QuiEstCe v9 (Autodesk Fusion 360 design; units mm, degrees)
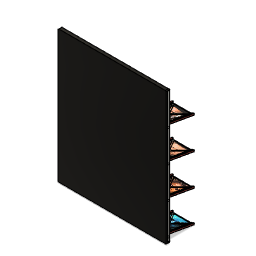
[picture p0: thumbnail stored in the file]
sketch "Esquisse1" plane through (0, 0, 0) normal (0, 1, 0) x axis (1, 0, 0)
  line L1 (15.9126, 24.8052) -> (-7.0874, 24.8052)
  line L2 (15.9126, -7.1948) -> (15.9126, 24.8052)
  line L3 (-7.0874, -7.1948) -> (15.9126, -7.1948)
  line L4 (-7.0874, 24.8052) -> (-7.0874, -7.1948)
  line L5 (16.9126, 25.8052) -> (-8.0874, 25.8052)
  line L6 (16.9126, -9.1948) -> (16.9126, 25.8052)
  line L7 (-8.0874, -9.1948) -> (16.9126, -9.1948)
  line L8 (-8.0874, 25.8052) -> (-8.0874, -9.1948)
  line L9 (-7.0874, 25.8052) -> (-7.0874, 24.8052)
  line L10 (15.9126, 25.8052) -> (15.9126, 24.8052)
  line L11 (14.9126, 24.8052) -> (-6.0874, 24.8052)
  line L12 (14.9126, -7.1948) -> (14.9126, 24.8052)
  line L13 (-6.0874, -7.1948) -> (14.9126, -7.1948)
  line L14 (-6.0874, 24.8052) -> (-6.0874, -7.1948)
  line L15 (15, -7.1948) -> (-7.0874, -7.1948)
  line L16 (15, -8.1948) -> (15, -7.1948)
  line L17 (-7.0874, -8.1948) -> (15, -8.1948)
  line L18 (-7.0874, -7.1948) -> (-7.0874, -8.1948)
  line L19 (13.9126, -7.1948) -> (-6.0874, 23.8052)
  line L20 (14.9126, -6.1948) -> (-5.0874, 24.8052)
  line L21 (-6.0874, -6.1948) -> (13.9126, 24.8052)
  line L22 (14.9126, 23.8052) -> (-5.0874, -7.1948)
  line L23 (14.6866, 25.7994) -> (-5.8002, 25.7994)
  line L24 (15.6866, -7.1031) -> (15.6866, 24.7994)
  line L25 (-5.8002, -8.1031) -> (14.6866, -8.1031)
  line L26 (-6.8002, 24.7994) -> (-6.8002, -7.1031)
  arc A1 centre (-5.8002, 24.7994) radius 1 clockwise from (-6.8002, 24.7994) to (-5.8002, 25.7994)
  arc A2 centre (14.6866, 24.7994) radius 1 clockwise from (14.6866, 25.7994) to (15.6866, 24.7994)
  arc A3 centre (-5.8002, -7.1031) radius 1 clockwise from (-5.8002, -8.1031) to (-6.8002, -7.1031)
  arc A4 centre (14.6866, -7.1031) radius 1 clockwise from (15.6866, -7.1031) to (14.6866, -8.1031)
  point P10 (-7.0874, 25.8052)
  point P11 (15.9126, 25.8052)
  point P14 (14.9126, -7.1948)
  point P12 (-6.0874, 24.8052)
  point P19 (-6.0874, 23.8052)
  point P20 (13.9126, -7.1948)
  point P21 (-5.0874, 24.8052)
  point P22 (14.9126, -6.1948)
  point P23 (13.9126, 24.8052)
  point P24 (-6.0874, -6.1948)
  point P25 (-5.0874, -7.1948)
  point P26 (14.9126, 23.8052)
  horizontal L1
  vertical L2
  horizontal L3
  vertical L4
  horizontal L5
  vertical L6
  horizontal L7
  vertical L8
  coincident L5 P10
  perpendicular L5 L9
  coincident L5 P11
  perpendicular L5 L10
  horizontal L11
  vertical L12
  horizontal L13
  vertical L14
  coincident L3 P14
  coincident L1 P12
  horizontal L15
  vertical L16
  horizontal L17
  vertical L18
  coincident L14 P19
  coincident L15 P20
  coincident L1 P21
  coincident L12 P22
  parallel L19 L20
  coincident L1 P23
  coincident L14 P24
  coincident L15 P25
  coincident L12 P26
  parallel L21 L22
  horizontal L23
  vertical L24
  horizontal L25
  vertical L26
  tangent L23 A1
  tangent L26 A1
  tangent L23 A2
  tangent L24 A2
  equal A1 A2
  tangent L26 A3
  tangent L25 A3
  equal A1 A3
  tangent L25 A4
  tangent L24 A4
  equal A1 A4
  dimension "d5" distance L4 L14 = 1
  dimension "d6" distance L2 L12 = 1
  dimension "d7" distance L4 L8 = 1
  dimension "d8" distance L2 L6 = 1
  dimension "d11" distance L3 L17 = 1
  dimension "d18" distance L6 L8 = 25
  dimension "d19" distance L5 L7 = 35
  dimension "d20" distance L7 L17 = 1
  dimension "d21" distance L5 L11 = 1
  dimension "d24" distance L11 P26 = 1
  dimension "d25" distance L12 P23 = 1
  dimension "d26" distance L14 P21 = 1
  dimension "d27" distance L1 P19 = 1
  dimension "d28" distance L3 P24 = 1
  dimension "d29" distance L15 P22 = 1
  dimension "d75" radius A1 = 1
extrude "Extrusion1" new body sketch "Esquisse1" profile of L1 L2 L3 L4 L5 L6 L7 L8 L9 L10 L11 L12 L13 L14 L15 L16 L17 L18 L19 L20 L21 L22 against normal blind 1
extrude "Extrusion2" add sketch "Esquisse1" profile of L1 L2 L3 L4 L5 L6 L7 L8 L9 L10 L12 L13 L14 along normal blind 1.5
extrude "Extrusion3" cut sketch "Esquisse1" profile of L1 L2 L3 L4 L12 L13 L14 L15 L16 L17 L18 along normal blind 1
chamfer "Chanfrein" distance 0.4 Rotate Angle 80
sketch "Esquisse2" plane through (16.9126, 0, 0) normal (1, 0, 0) x axis (0, 0, -1)
  line L1 (-9.1948, 1.2685) -> (-9.1948, 1.5)
  line L2 (25.8052, -1) -> (-8.7948, -1)
  line L3 (25.8052, 1.5) -> (25.8052, -1)
  line L4 (-9.1948, 1.5) -> (25.8052, 1.5)
  line L5 (-6.6948, 1.5) -> (-7.7948, 1.5)
  line L6 (-6.6948, -1) -> (-6.6948, 1.5)
  line L7 (-9.1948, -1) -> (-6.6948, -1)
  line L8 (-9.1948, 0.1) -> (-9.1948, -1)
  line L9 (-6.6948, -1) -> (-9.1948, 1.5)
  line L10 (-8.7948, -1) -> (-6.6948, 1.5)
  line L11 (-8.7948, -1) -> (-9.1948, 1.2685)
  circle C1 centre (-7.7448, 0.25) radius 0.75
  arc A1 centre (-7.7948, 0.1) radius 1.4 clockwise from (-9.1948, 0.1) to (-7.7948, 1.5)
  point P7 (-6.6948, -1)
  point P2 (-9.1948, 1.5)
  point P9 (-9.1948, 1.5)
  point P3 (-8.7948, -1)
  point P10 (-8.7948, -1)
  point P11 (-7.7448, 0.25)
  horizontal L5
  vertical L6
  horizontal L7
  vertical L8
  coincident L2 P7
  coincident P2 P9
  coincident P3 P10
  midpoint L10 P11
  tangent L8 A1
  tangent L5 A1
  dimension "d12" distance L6 L8 = 2.5
  dimension "d13" diameter C1 = 1.5
  dimension "d43" radius A1 = 1.4
extrude "Extrusion4" new body sketch "Esquisse2" profile of C1 along normal blind 1.5
extrude "Extrusion10" cut sketch "Esquisse2" profile of L1 L4 L11 A1 against normal blind 25.2
fillet "Congé1" radius 0.5
copy_paste_bodies "Copier/Coller des corps1"
move "Déplacer1"
combine "Combiner1"
move "Déplacer2"
combine "Combiner2"
fillet "Congé5" radius 1
fillet "Congé6" radius 1.25
fillet "Congé7" radius 0.4
move "Déplacer3"
copy_paste_bodies "Copier/Coller des corps2"
move "Déplacer4"
copy_paste_bodies "Copier/Coller des corps3"
move "Déplacer5"
copy_paste_bodies "Copier/Coller des corps4"
move "Déplacer6"
move "Déplacer7"
copy_paste_bodies "Copier/Coller des corps5"
move "Déplacer8"
copy_paste_bodies "Copier/Coller des corps6"
move "Déplacer9"
copy_paste_bodies "Copier/Coller des corps7"
move "Déplacer10"
extrude "Extrusion5" new body blind 1.5
sketch "Esquisse4" plane through (0, 37.8052, 0) normal (0, 1, 0) x axis (-1, 0, 0)
  line L1 (97.0874, 0) -> (-25.9126, 0)
  line L2 (97.0874, 1.5) -> (97.0874, 0)
  line L3 (-25.9126, 1.5) -> (97.0874, 1.5)
  line L4 (-25.9126, 0) -> (-25.9126, 1.5)
  line L5 (93.5874, 0) -> (97.0874, 0)
  line L6 (93.5874, -2.5) -> (93.5874, 0)
  line L7 (96.5874, -3) -> (94.0874, -3)
  line L8 (97.0874, 0) -> (97.0874, -2.5)
  line L9 (64.0874, -3) -> (67.0874, -3)
  line L10 (63.5874, 0) -> (63.5874, -2.5)
  line L11 (67.5874, 0) -> (63.5874, 0)
  line L12 (67.5874, -2.5) -> (67.5874, 0)
  line L13 (33.5874, 0) -> (37.5874, 0)
  line L14 (33.5874, -2.5) -> (33.5874, 0)
  line L15 (37.0874, -3) -> (34.0874, -3)
  line L16 (37.5874, 0) -> (37.5874, -2.5)
  line L17 (3.5874, 0) -> (7.5874, 0)
  line L18 (3.5874, -2.5) -> (3.5874, 0)
  line L19 (7.0874, -3) -> (4.0874, -3)
  line L20 (7.5874, 0) -> (7.5874, -2.5)
  line L21 (-22.4126, 0) -> (-25.9126, 0)
  line L22 (-22.4126, -2.5) -> (-22.4126, 0)
  line L23 (-25.4126, -3) -> (-22.9126, -3)
  line L24 (-25.9126, 0) -> (-25.9126, -2.5)
  line L25 (-24.4, -3) -> (96.6703, -3)
  line L26 (-25.4126, 0) -> (-25.4126, -3)
  line L27 (3.0874, -23.8052) -> (3.0874, 9.0481)
  line L28 (-21.9126, 9.0377) -> (-21.9126, -23.8052)
  line L29 (93.0874, -23.8052) -> (93.0874, 9.0481)
  line L30 (63.0874, -23.8052) -> (63.0874, 9.0481)
  line L31 (68.0874, 9.0377) -> (68.0874, -23.8052)
  line L32 (38.0874, 9.0377) -> (38.0874, -23.8052)
  line L33 (97.0874, 0) -> (-25.9126, 0)
  arc A1 centre (96.5874, -2.5) radius 0.5 clockwise from (97.0874, -2.5) to (96.5874, -3)
  arc A2 centre (94.0874, -2.5) radius 0.5 clockwise from (94.0874, -3) to (93.5874, -2.5)
  arc A3 centre (67.0874, -2.5) radius 0.5 clockwise from (67.5874, -2.5) to (67.0874, -3)
  arc A4 centre (64.0874, -2.5) radius 0.5 clockwise from (64.0874, -3) to (63.5874, -2.5)
  arc A5 centre (37.0874, -2.5) radius 0.5 clockwise from (37.5874, -2.5) to (37.0874, -3)
  arc A6 centre (34.0874, -2.5) radius 0.5 clockwise from (34.0874, -3) to (33.5874, -2.5)
  arc A7 centre (7.0874, -2.5) radius 0.5 clockwise from (7.5874, -2.5) to (7.0874, -3)
  arc A8 centre (4.0874, -2.5) radius 0.5 clockwise from (4.0874, -3) to (3.5874, -2.5)
  arc A9 centre (-22.9126, -2.5) radius 0.5 clockwise from (-22.4126, -2.5) to (-22.9126, -3)
  arc A10 centre (-25.4126, -2.5) radius 0.5 clockwise from (-25.4126, -3) to (-25.9126, -2.5)
  point P3 (97.0874, 0)
  point P6 (97.0874, 0)
  point P8 (63.5874, 0)
  point P10 (37.5874, 0)
  point P12 (7.5874, 0)
  point P2 (-25.9126, 0)
  point P14 (-25.9126, 0)
  point P46 (96.6703, -3)
  point P47 (-24.4, -3)
  point P48 (-25.4126, 0)
  horizontal L5
  vertical L6
  horizontal L7
  vertical L8
  coincident P3 P6
  horizontal L9
  vertical L10
  horizontal L11
  vertical L12
  coincident L1 P8
  horizontal L13
  vertical L14
  horizontal L15
  vertical L16
  coincident L1 P10
  horizontal L17
  vertical L18
  horizontal L19
  vertical L20
  coincident L1 P12
  horizontal L21
  vertical L22
  horizontal L23
  vertical L24
  coincident P2 P14
  tangent L8 A1
  tangent L7 A1
  tangent L7 A2
  tangent L6 A2
  equal A1 A2
  tangent L12 A3
  tangent L9 A3
  equal A1 A3
  tangent L9 A4
  tangent L10 A4
  equal A1 A4
  tangent L16 A5
  tangent L15 A5
  equal A1 A5
  tangent L15 A6
  tangent L14 A6
  equal A1 A6
  tangent L20 A7
  tangent L19 A7
  equal A1 A7
  tangent L19 A8
  tangent L18 A8
  equal A1 A8
  tangent L22 A9
  tangent L23 A9
  equal A1 A9
  tangent L23 A10
  tangent L24 A10
  equal A1 A10
  coincident L7 P46
  coincident L23 P47
  perpendicular L6 L25
  coincident L21 P48
  collinear L9 L25
  collinear L19 L25
  collinear L15 L25
  parallel L22 L26
  dimension "d34" radius A1 = 0.5
  dimension "d93" distance L18 L27 = 0.5
  dimension "d94" distance L22 L28 = 0.5
  dimension "d95" distance L6 L29 = 0.5
  dimension "d96" distance L10 L30 = 0.5
  dimension "d97" distance L12 L31 = 0.5
  dimension "d98" distance L16 L32 = 0.5
  dimension "d100" distance L14 L32 = 4.5
  dimension "d101" distance L20 L27 = 4.5
  dimension "d116" distance L25 L33 = 3
extrude "Extrusion6" new body sketch "Esquisse4" profile of L1 L5 L6 L7 L8 L9 L10 L11 L12 L13 L14 L15 L16 L17 L18 L19 L20 L21 L22 L23 A1 A2 A3 A4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 against normal blind 151
extrude "Extrusion7" new body sketch "Esquisse4" profile of L1 L5 L6 L7 L8 L9 L10 L11 L12 L13 L14 L15 L16 L17 L18 L19 L20 L21 L22 L23 L24 A1 A2 A3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 against normal blind 1
copy_paste_bodies "Copier/Coller des corps8"
move "Déplacer11"
combine "Combiner3"
sketch "Esquisse5" plane through (25.9126, 0, 0) normal (1, 0, 0) x axis (0, 0, -1)
  line L1 (2.5, -113.0748) -> (0, -113.0748)
  line L2 (2.5, 37.8052) -> (2.5, 36.8052)
  line L3 (-1.5, 37.8052) -> (2.5, 37.8052)
  line L4 (-1.5, -113.0847) -> (-1.5, 37.8052)
  line L5 (0, -113.0847) -> (-1.5, -113.0847)
  line L6 (0, -112.0748) -> (2.5, -112.0748)
  line L7 (0, 36.8052) -> (0, -112.0748)
  line L8 (2.5, 36.8052) -> (0, 36.8052)
  line L9 (2.5, -112.0748) -> (2.5, -113.0748)
  line L10 (0, -113.0748) -> (0, -113.0847)
  circle C1 centre (1.25, 0.25) radius 0.9074
  circle C2 centre (1.25, -29.75) radius 0.9074
  circle C3 centre (1.25, -59.55) radius 0.905
  circle C4 centre (1.25, -89.75) radius 0.9074
move "Déplacer32"
extrude "Extrusion9" new body of existing geometry blind 148.8 bodies "Fermeture"
fillet "Congé4" radius 1
rectangular_pattern "Réseau R1" uSpaceDistance -90 vSpaceDistance 0
rectangular_pattern "Réseau R2" uSpaceDistance -90 vSpaceDistance 0
rectangular_pattern "Réseau R3" uSpaceDistance -90 vSpaceDistance 0
move "Déplacer12" RotateAngle 10
move "Déplacer13" RotateAngle 10
move "Déplacer14" RotateAngle 10
move "Déplacer15" RotateAngle 100
move "Déplacer16" RotateAngle 10
move "Déplacer17" RotateAngle 10
move "Déplacer18" RotateAngle 10
move "Déplacer33"
move "Déplacer34" RotateAngle -10
move "Déplacer35" RotateAngle -10
move "Déplacer36" RotateAngle -10
move "Déplacer37" RotateAngle -10
move "Déplacer38" RotateAngle -10
extrude "Extrusion11" new body sketch "Esquisse1" profile of L19 L20 L21 L22 L23 L24 L25 L26 A1 A2 A3 A4 along normal blind 0.1 bodies "Carte"
move "Déplacer39"
move "Déplacer40"
move "Déplacer41"
move "Déplacer42"
move "Déplacer43" RotateAngle 100
move "Déplacer44" RotateAngle -100
move "Déplacer45"
move "Déplacer46"
move "Déplacer47"
move "Déplacer48" RotateAngle -10
move "Déplacer49" RotateAngle -100
move "Déplacer50"
move "Déplacer51"
move "Déplacer52"
move "Déplacer25"
move "Déplacer26"
sketch "Esquisse6" plane through (25.4126, 0, 0) normal (1, 0, 0) x axis (0, 0, -1)
  line L1 (-8.2, -112.0748) -> (-11.2, -112.0748)
  line L2 (-8.2, 36.8052) -> (-8.2, -112.0748)
  line L3 (-11.2, 36.8052) -> (-8.2, 36.8052)
  line L4 (-11.2, -112.0748) -> (-11.2, 36.8052)
  circle C1 centre (-9.7221, 0.25) radius 1
  circle C2 centre (-9.7522, -35.7518) radius 0.9989
  circle C3 centre (-9.7522, -71.7518) radius 0.9989
  circle C4 centre (-9.7522, -107.7518) radius 0.9989
  dimension "d111" diameter C1 = 2
extrude "Extrusion12" cut sketch "Esquisse6" profile of C1 C2 C3 C4 against normal blind 119 and along normal blind 4
decal "Décalcomanie1"
rectangular_pattern "Réseau R4" uSpaceDistance -108 vSpaceDistance 90 bodies "Carte (1)", "Carte (2)", "Carte (3)", "Carte (4)", "Carte (5)", "Carte (6)", "Carte (7)", "Carte (8)"
decal "Décalcomanie2"
decal "Décalcomanie3"
decal "Décalcomanie4"
decal "Décalcomanie5"
decal "Décalcomanie6"
decal "Décalcomanie7"
decal "Décalcomanie8"
decal "Décalcomanie9"
decal "Décalcomanie10"
decal "Décalcomanie11"
decal "Décalcomanie12"
decal "Décalcomanie13"
move "Déplacer53" RotateAngle -100
move "Déplacer54" RotateAngle 100
decal "Décalcomanie14"
decal "Décalcomanie15"
offset_faces "DécalerLesFaces" distance 0.1
fillet "Congé8" radius 0.5
move "Déplacer27"
move "Déplacer28"
move "Déplacer29"
move "Déplacer30"
move "Déplacer31"
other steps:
base_feature "Fonction de base1"
base_feature "Fonction de base2"
base_feature "Fonction de base3"
base_feature "Fonction de base4"
base_feature "Fonction de base5"
base_feature "Fonction de base6" bodies "Pion_Perce"
base_feature "Fonction de base7"
base_feature "Fonction de base8" bodies "Plateau"
named bodies: "Pion_Perce", "Plateau", "Fermeture", "Carte", "Carte (1)", "Carte (2)", "Carte (3)", "Carte (4)", "Carte (5)", "Carte (6)", "Carte (7)", "Carte (8)", "Carte (9)", "Carte (10)", "Carte (11)", "Carte (12)", "Carte (13)", "Carte (14)", "Carte (15)"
